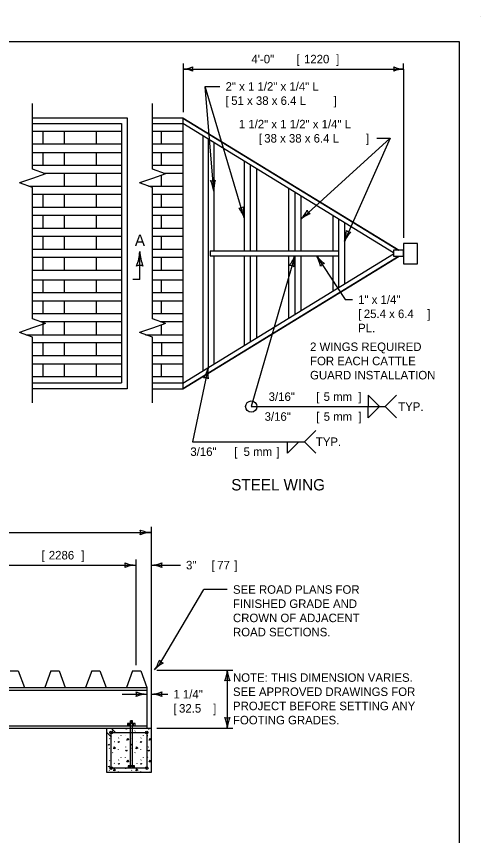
# Model space of a CAD drawing. Extents: x 49991.4 to 50021, y 49987.6 to 50011.4.
# Drawn here: x 50013.63 to 50016.9, y 49993.4 to 49999.18 of the extents above; entities that cross this region are included whole.
import ezdxf

# ---------------------------------------------------------------- set-up
doc = ezdxf.new("R2010")
doc.units = 0
for name, color, linetype in [('Level 1', 7, 'Continuous'), ('Level 2', 7, 'Continuous'), ('Level 3', 7, 'Continuous'), ('Level 4', 7, 'Continuous'), ('Level 6', 7, 'Continuous')]:
    doc.layers.add(name, color=color, linetype=linetype)

msp = doc.modelspace()

# ---------------------------------------------------------------- linework, layer by layer
at = {"layer": 'Level 1'}
for p, q in [((50016.9001, 49999.1756), (50016.9001, 49999.1756)), ((50013.7456, 49998.4611), (50014.4107, 49998.4611)), ((50014.4107, 49998.4611), (50014.4107, 49996.5518)), ((50014.5891, 49998.4611), (50014.8029, 49998.4611)), ((50014.8029, 49998.4611), (50016.3256, 49997.5269)), ((50014.8029, 49998.4611), (50014.8029, 49996.5517)), ((50013.7456, 49998.4211), (50014.3707, 49998.4211)), ((50014.3707, 49998.4211), (50014.3707, 49996.5923)), ((50014.5891, 49998.4211), (50014.8029, 49998.4211)), ((50014.8029, 49998.4223), (50016.2874, 49997.5115)), ((50014.3707, 49998.3652), (50013.7456, 49998.3652)), ((50013.8192, 49998.2744), (50013.8192, 49998.3652)), ((50013.9701, 49998.2744), (50013.9701, 49998.3652)), ((50014.1943, 49998.2744), (50014.1943, 49998.3652)), ((50014.8029, 49998.3652), (50014.5891, 49998.3652)), ((50014.6527, 49998.2744), (50014.6527, 49998.3652)), ((50014.9451, 49998.3351), (50014.9451, 49996.6777)), ((50014.3707, 49998.2744), (50013.7456, 49998.2744)), ((50014.8029, 49998.2744), (50014.5891, 49998.2744)), ((50014.9816, 49998.3127), (50014.9816, 49996.7001)), ((50015.0211, 49998.2884), (50015.0211, 49997.5238)), ((50013.7456, 49998.2165), (50014.3707, 49998.2165)), ((50013.8192, 49998.1264), (50013.8192, 49998.2165)), ((50013.9701, 49998.1264), (50013.9701, 49998.2165)), ((50014.1943, 49998.1264), (50014.1943, 49998.2165)), ((50014.5891, 49998.2165), (50014.8029, 49998.2165)), ((50014.6527, 49998.1264), (50014.6527, 49998.2165)), ((50015.2358, 49998.1567), (50015.2358, 49997.5238)), ((50013.7456, 49998.1264), (50014.3707, 49998.1264)), ((50014.5891, 49998.1264), (50014.8029, 49998.1264)), ((50015.2784, 49998.1306), (50015.2784, 49997.5238)), ((50015.321, 49998.1044), (50015.321, 49997.5238)), ((50013.8277, 49998.0696), (50014.3707, 49998.0696)), ((50013.9701, 49997.9788), (50013.9701, 49998.0696)), ((50014.1943, 49997.9788), (50014.1943, 49998.0696)), ((50014.6527, 49997.9788), (50014.6527, 49998.0563)), ((50014.6709, 49998.0696), (50014.8029, 49998.0696)), ((50013.7182, 49997.9788), (50014.3707, 49997.9788)), ((50014.5615, 49997.9788), (50014.8029, 49997.9788)), ((50013.7456, 49997.9219), (50014.3707, 49997.9219)), ((50013.8192, 49997.831), (50013.8192, 49997.9219)), ((50013.9701, 49997.831), (50013.9701, 49997.9219)), ((50014.1943, 49997.831), (50014.1943, 49997.9219)), ((50014.5891, 49997.9219), (50014.8029, 49997.9219)), ((50014.6527, 49997.831), (50014.6527, 49997.9219)), ((50015.5482, 49997.965), (50015.5482, 49997.5238)), ((50015.5908, 49997.9389), (50015.5908, 49997.5238)), ((50015.6336, 49997.9127), (50015.6336, 49997.5238)), ((50013.7456, 49997.831), (50014.3707, 49997.831)), ((50014.5891, 49997.831), (50014.8029, 49997.831)), ((50013.7456, 49997.7742), (50014.3707, 49997.7742)), ((50013.8192, 49997.6832), (50013.8192, 49997.7742)), ((50013.9701, 49997.6832), (50013.9701, 49997.7742)), ((50014.1943, 49997.6832), (50014.1943, 49997.7742)), ((50014.5891, 49997.7742), (50014.8029, 49997.7742)), ((50014.6527, 49997.6832), (50014.6527, 49997.7742)), ((50015.8607, 49997.7733), (50015.8607, 49997.5238)), ((50015.9006, 49997.7488), (50015.9006, 49997.2639)), ((50013.7456, 49997.6832), (50014.3707, 49997.6832)), ((50014.5891, 49997.6832), (50014.8029, 49997.6832)), ((50015.9409, 49997.7241), (50015.9409, 49997.2886)), ((50013.7456, 49997.6265), (50014.3707, 49997.6265)), ((50013.8192, 49997.5355), (50013.8192, 49997.6265)), ((50013.9701, 49997.5355), (50013.9701, 49997.6265)), ((50014.1943, 49997.5355), (50014.1943, 49997.6265)), ((50014.5891, 49997.6265), (50014.8029, 49997.6265)), ((50014.6527, 49997.5355), (50014.6527, 49997.6265)), ((50013.7456, 49997.5355), (50014.3707, 49997.5355)), ((50014.5891, 49997.5355), (50014.8029, 49997.5355)), ((50014.9948, 49997.5238), (50015.9006, 49997.5238)), ((50014.9948, 49997.5238), (50014.9948, 49997.489)), ((50013.7456, 49997.4788), (50014.3707, 49997.4788)), ((50013.8192, 49997.3862), (50013.8192, 49997.4788)), ((50013.9701, 49997.3862), (50013.9701, 49997.4788)), ((50014.1943, 49997.3862), (50014.1943, 49997.4788)), ((50014.5891, 49997.4788), (50014.8029, 49997.4788)), ((50014.6527, 49997.3862), (50014.6527, 49997.4788)), ((50014.8029, 49996.5904), (50016.2874, 49997.5012)), ((50014.8029, 49996.5517), (50016.3256, 49997.486)), ((50014.9948, 49997.489), (50015.9006, 49997.489)), ((50015.0211, 49997.489), (50015.0211, 49996.7243)), ((50015.2358, 49997.489), (50015.2358, 49996.856)), ((50015.2784, 49997.489), (50015.2784, 49996.8822)), ((50015.321, 49997.489), (50015.321, 49996.9083)), ((50015.5482, 49997.489), (50015.5482, 49997.0477)), ((50015.5908, 49997.489), (50015.5908, 49997.0738)), ((50015.6336, 49997.489), (50015.6336, 49997.1001)), ((50015.8607, 49997.489), (50015.8607, 49997.2394)), ((50013.7456, 49997.3862), (50014.3707, 49997.3862)), ((50014.5891, 49997.3862), (50014.8029, 49997.3862)), ((50013.7456, 49997.3196), (50014.3707, 49997.3196)), ((50013.8192, 49997.2287), (50013.8192, 49997.3196)), ((50013.9701, 49997.2287), (50013.9701, 49997.3196)), ((50014.1943, 49997.2287), (50014.1943, 49997.3196)), ((50014.5891, 49997.3196), (50014.8029, 49997.3196)), ((50014.6527, 49997.2287), (50014.6527, 49997.3196)), ((50013.7456, 49997.2287), (50014.3707, 49997.2287)), ((50014.5891, 49997.2287), (50014.8029, 49997.2287)), ((50013.7456, 49997.1719), (50014.3707, 49997.1719)), ((50013.8192, 49997.081), (50013.8192, 49997.1719)), ((50013.9701, 49997.081), (50013.9701, 49997.1719)), ((50014.1943, 49997.081), (50014.1943, 49997.1719)), ((50014.5891, 49997.1719), (50014.8029, 49997.1719)), ((50014.6527, 49997.081), (50014.6527, 49997.1719)), ((50013.7456, 49997.081), (50014.3707, 49997.081)), ((50014.5891, 49997.081), (50014.8029, 49997.081)), ((50013.8023, 49997.0242), (50014.3707, 49997.0242)), ((50013.8192, 49996.9316), (50013.8192, 49997.0242)), ((50013.9701, 49996.9316), (50013.9701, 49997.0242)), ((50014.1943, 49996.9316), (50014.1943, 49997.0242)), ((50014.6447, 49997.0242), (50014.8029, 49997.0242)), ((50014.6527, 49996.9316), (50014.6527, 49997.0016)), ((50013.6979, 49996.9316), (50014.3707, 49996.9316)), ((50013.7456, 49996.8766), (50014.3707, 49996.8766)), ((50013.8192, 49996.7855), (50013.8192, 49996.8766)), ((50013.9701, 49996.7855), (50013.9701, 49996.8766)), ((50014.1943, 49996.7855), (50014.1943, 49996.8766)), ((50014.5403, 49996.9316), (50014.8029, 49996.9316)), ((50014.5891, 49996.8766), (50014.8029, 49996.8766)), ((50014.6527, 49996.8766), (50014.6527, 49996.7855)), ((50013.7456, 49996.7855), (50014.3707, 49996.7855)), ((50014.5891, 49996.7855), (50014.8029, 49996.7855)), ((50013.7456, 49996.7279), (50014.3707, 49996.7279)), ((50013.8192, 49996.6378), (50013.8192, 49996.7279)), ((50013.9701, 49996.6378), (50013.9701, 49996.7279)), ((50014.1943, 49996.6378), (50014.1943, 49996.7279)), ((50014.5891, 49996.7279), (50014.8029, 49996.7279)), ((50014.6527, 49996.6378), (50014.6527, 49996.7279)), ((50013.7456, 49996.6378), (50014.3707, 49996.6378)), ((50013.7456, 49996.5923), (50014.3707, 49996.5923)), ((50014.5891, 49996.6378), (50014.8029, 49996.6378)), ((50014.5891, 49996.5923), (50014.8029, 49996.5923)), ((50013.7456, 49996.5523), (50014.4107, 49996.5523)), ((50014.5891, 49996.5517), (50014.8019, 49996.5517)), ((50014.8019, 49996.5517), (50014.8029, 49996.5517)), ((50013.5871, 49994.5622), (50013.6444, 49994.5622)), ((50013.6444, 49994.5622), (50013.6877, 49994.4468)), ((50013.8746, 49994.5622), (50013.8312, 49994.4468)), ((50013.8746, 49994.5622), (50013.9319, 49994.5622)), ((50013.9319, 49994.5622), (50013.9752, 49994.4468)), ((50014.162, 49994.5622), (50014.1186, 49994.4468)), ((50014.162, 49994.5622), (50014.2194, 49994.5622)), ((50014.2194, 49994.5622), (50014.2628, 49994.4468)), ((50014.4495, 49994.5635), (50014.4056, 49994.4468)), ((50014.4495, 49994.5635), (50014.507, 49994.5635)), ((50014.507, 49994.5635), (50014.5501, 49994.4468)), ((50010.9693, 49994.4468), (50014.5501, 49994.4468)), ((50010.9693, 49994.4271), (50014.5501, 49994.4271)), ((50014.5501, 49994.4468), (50014.5501, 49994.1596)), ((50010.9693, 49994.1748), (50014.5501, 49994.1748)), ((50014.4097, 49994.1756), (50014.4722, 49994.1756)), ((50014.4097, 49994.1748), (50014.4097, 49994.1756)), ((50014.4498, 49994.1926), (50014.414, 49994.1926)), ((50014.414, 49994.1926), (50014.414, 49994.1756)), ((50014.4247, 49994.1756), (50014.4247, 49994.1926)), ((50014.4341, 49993.8798), (50014.4341, 49994.2114)), ((50014.4498, 49994.2103), (50014.4341, 49994.2114)), ((50014.4498, 49994.2073), (50014.4341, 49994.2084)), ((50014.4498, 49994.2044), (50014.4341, 49994.2055)), ((50014.4498, 49994.2014), (50014.4341, 49994.2025)), ((50014.4498, 49994.1984), (50014.4341, 49994.1995)), ((50014.4498, 49994.1955), (50014.4341, 49994.1966)), ((50014.4498, 49993.8801), (50014.4498, 49994.2103)), ((50014.4678, 49994.1926), (50014.4498, 49994.1926)), ((50014.4566, 49994.1756), (50014.4566, 49994.1926)), ((50014.4678, 49994.1756), (50014.4678, 49994.1926)), ((50014.4722, 49994.1748), (50014.4722, 49994.1756)), ((50010.9398, 49994.1596), (50014.5796, 49994.1596)), ((50014.2673, 49994.1284), (50014.3005, 49994.0951)), ((50014.2986, 49994.1596), (50014.3317, 49994.1264)), ((50014.448, 49993.8944), (50014.4192, 49993.894)), ((50014.4192, 49993.894), (50014.4194, 49993.8795)), ((50014.4194, 49993.8795), (50014.4482, 49993.8801)), ((50014.4283, 49993.8796), (50014.428, 49993.8942)), ((50014.4624, 49993.8947), (50014.448, 49993.8944)), ((50014.4482, 49993.8801), (50014.4626, 49993.8803)), ((50014.4536, 49993.8803), (50014.4534, 49993.8946)), ((50014.4626, 49993.8803), (50014.4624, 49993.8947))]:
    msp.add_line(p, q, dxfattribs=at)
for points in [[(49999.3835, 49998.9992), (50016.7501, 49998.9992), (50016.7501, 49987.7988), (49999.3835, 49987.7988)], [(50016.3578, 49997.5749), (50016.3578, 49997.4326), (50016.4569, 49997.4326), (50016.4569, 49997.5749)], [(50016.2874, 49997.5269), (50016.2874, 49997.486), (50016.3578, 49997.486), (50016.3578, 49997.5269)], [(50014.2673, 49994.1596), (50014.5798, 49994.1596), (50014.5798, 49993.8471), (50014.2673, 49993.8471)], [(50014.2986, 49994.1284), (50014.5486, 49994.1284), (50014.5486, 49993.8784), (50014.2986, 49993.8784)]]:
    msp.add_lwpolyline(points, close=True, dxfattribs=at)
for centre in [(50014.2986, 49994.1283), (50014.5486, 49994.1283), (50014.2986, 49993.8783), (50014.5486, 49993.8783)]:
    msp.add_circle(centre, 0.00937, dxfattribs=at)
at = {"layer": 'Level 3'}
for p, q in [((50014.8046, 49998.8446), (50014.8046, 49998.5011)), ((50016.3573, 49998.8046), (50016.3573, 49998.8446)), ((50016.3573, 49998.8046), (50016.3573, 49998.4863)), ((50016.3573, 49998.4863), (50016.3573, 49997.6149)), ((50016.2623, 49998.3163), (50015.6336, 49997.7451)), ((50016.2623, 49998.3163), (50015.9409, 49997.5909)), ((50016.1701, 49998.3163), (50016.2623, 49998.3163)), ((50015.5908, 49997.489), (50015.2854, 49996.4255)), ((50015.7449, 49997.489), (50015.9457, 49997.1793)), ((50015.9457, 49997.1793), (50015.9977, 49997.1793)), ((50014.9816, 49996.7001), (50014.8702, 49996.1778)), ((50016.1082, 49996.5055), (50016.1082, 49996.4255)), ((50016.1082, 49996.5055), (50016.1882, 49996.4255)), ((50016.2282, 49996.4255), (50016.3082, 49996.5055)), ((50015.2854, 49996.4255), (50016.2282, 49996.4255)), ((50016.1082, 49996.3455), (50016.1082, 49996.4255)), ((50016.1082, 49996.3455), (50016.1882, 49996.4255)), ((50016.2282, 49996.4255), (50016.3082, 49996.3455)), ((50015.6598, 49996.1778), (50015.7398, 49996.2578)), ((50014.8702, 49996.1778), (50015.6598, 49996.1778)), ((50015.5398, 49996.0978), (50015.5398, 49996.1778)), ((50015.5398, 49996.0978), (50015.6198, 49996.1778)), ((50015.6598, 49996.1778), (50015.7398, 49996.0978)), ((50014.5798, 49995.579), (50014.5798, 49994.1996)), ((50010.938, 49995.539), (50014.5798, 49995.539)), ((50014.4721, 49995.3483), (50014.4721, 49994.6035)), ((50011.04, 49995.3083), (50014.4721, 49995.3083)), ((50014.5798, 49995.3083), (50014.7857, 49995.3083)), ((50014.6316, 49994.5968), (50014.9515, 49995.1364)), ((50015.1164, 49995.1364), (50014.9515, 49995.1364)), ((50014.6198, 49994.5687), (50015.1564, 49994.5687)), ((50015.1164, 49994.5687), (50015.1164, 49994.1591)), ((50014.3767, 49994.399), (50014.5501, 49994.399)), ((50014.5798, 49994.3988), (50014.6969, 49994.3988)), ((50014.5798, 49994.1996), (50014.5798, 49994.1596)), ((50014.3088, 49994.1389), (50014.3099, 49994.1413)), ((50014.3661, 49994.1089), (50014.3672, 49994.1073)), ((50014.3972, 49994.1083), (50014.3982, 49994.1067)), ((50014.4664, 49994.1389), (50014.4675, 49994.1413)), ((50014.5237, 49994.1089), (50014.5248, 49994.1073)), ((50014.5548, 49994.1083), (50014.5559, 49994.1067)), ((50014.6196, 49994.1591), (50015.1564, 49994.1591)), ((50014.2873, 49994.083), (50014.2883, 49994.0854)), ((50014.3206, 49994.066), (50014.3216, 49994.0644)), ((50014.3485, 49994.0591), (50014.3517, 49994.0657)), ((50014.357, 49994.0617), (50014.3485, 49994.0591)), ((50014.3504, 49994.0892), (50014.3515, 49994.0916)), ((50014.3517, 49994.0657), (50014.357, 49994.0617)), ((50014.4449, 49994.083), (50014.4459, 49994.0854)), ((50014.4782, 49994.066), (50014.4792, 49994.0644)), ((50014.5061, 49994.0591), (50014.5093, 49994.0657)), ((50014.5147, 49994.0617), (50014.5061, 49994.0591)), ((50014.508, 49994.0892), (50014.5091, 49994.0916)), ((50014.5093, 49994.0657), (50014.5147, 49994.0617)), ((50014.2846, 49994.0154), (50014.2857, 49994.0178)), ((50014.3479, 49994.0087), (50014.3482, 49994.0063)), ((50014.4017, 49994.0263), (50014.4028, 49994.0287)), ((50014.4422, 49994.0154), (50014.4433, 49994.0178)), ((50014.5055, 49994.0087), (50014.5058, 49994.0063)), ((50014.5593, 49994.0263), (50014.5604, 49994.0287)), ((50014.2873, 49993.9286), (50014.2883, 49993.931)), ((50014.3088, 49993.9845), (50014.3099, 49993.9869)), ((50014.3504, 49993.9347), (50014.3515, 49993.9371)), ((50014.3661, 49993.9545), (50014.3672, 49993.9529)), ((50014.3972, 49993.9539), (50014.3982, 49993.9523)), ((50014.4449, 49993.9286), (50014.4459, 49993.931)), ((50014.4664, 49993.9845), (50014.4675, 49993.9869)), ((50014.508, 49993.9347), (50014.5091, 49993.9371)), ((50014.5237, 49993.9545), (50014.5248, 49993.9529)), ((50014.5548, 49993.9539), (50014.5559, 49993.9523)), ((50014.3206, 49993.9115), (50014.3216, 49993.9099)), ((50014.3485, 49993.9046), (50014.3517, 49993.9113)), ((50014.357, 49993.9073), (50014.3485, 49993.9046)), ((50014.3517, 49993.9113), (50014.357, 49993.9073)), ((50014.4017, 49993.8718), (50014.4028, 49993.8742)), ((50014.4782, 49993.9115), (50014.4792, 49993.9099)), ((50014.5061, 49993.9046), (50014.5093, 49993.9113)), ((50014.5147, 49993.9073), (50014.5061, 49993.9046)), ((50014.5093, 49993.9113), (50014.5147, 49993.9073)), ((50014.5593, 49993.8718), (50014.5604, 49993.8742)), ((50014.2846, 49993.8609), (50014.2857, 49993.8633)), ((50014.3479, 49993.8542), (50014.3482, 49993.8518)), ((50014.4422, 49993.8609), (50014.4433, 49993.8633)), ((50014.5055, 49993.8542), (50014.5058, 49993.8518))]:
    msp.add_line(p, q, dxfattribs=at)
for points in [[(50014.8046, 49998.8046), (50016.3573, 49998.8046)], [(50015.2358, 49997.7569), (50014.9617, 49998.6818)], [(50014.9617, 49998.6818), (50015.0642, 49998.6818)], [(50015.0211, 49997.9434), (50014.9617, 49998.6818)], [(50014.4022, 49994.1528), (50014.4054, 49994.1594), (50014.4108, 49994.1554), (50014.4022, 49994.1528)], [(50014.5599, 49994.1528), (50014.563, 49994.1594), (50014.5684, 49994.1554), (50014.5599, 49994.1528)], [(50014.2793, 49994.04), (50014.2825, 49994.0467), (50014.2878, 49994.0427), (50014.2793, 49994.04)], [(50014.4089, 49994.0758), (50014.4161, 49994.0894), (50014.4217, 49994.0769), (50014.4092, 49994.0758)], [(50014.4369, 49994.04), (50014.4401, 49994.0467), (50014.4454, 49994.0427), (50014.4369, 49994.04)], [(50014.5665, 49994.0758), (50014.5737, 49994.0894), (50014.5793, 49994.0769), (50014.5668, 49994.0758)], [(50014.317, 49994.0126), (50014.3191, 49994.0278), (50014.3286, 49994.018), (50014.3172, 49994.0127)], [(50014.4022, 49993.9983), (50014.4054, 49994.005), (50014.4108, 49994.001), (50014.4022, 49993.9983)], [(50014.4746, 49994.0126), (50014.4767, 49994.0278), (50014.4863, 49994.018), (50014.4749, 49994.0127)], [(50014.5599, 49993.9983), (50014.563, 49994.005), (50014.5684, 49994.001), (50014.5599, 49993.9983)], [(50014.4089, 49993.9214), (50014.4161, 49993.935), (50014.4217, 49993.9225), (50014.4092, 49993.9214)], [(50014.5665, 49993.9214), (50014.5737, 49993.935), (50014.5793, 49993.9225), (50014.5668, 49993.9214)], [(50014.2793, 49993.8856), (50014.2825, 49993.8922), (50014.2878, 49993.8882), (50014.2793, 49993.8856)], [(50014.317, 49993.8582), (50014.3191, 49993.8734), (50014.3286, 49993.8635), (50014.3172, 49993.8583)], [(50014.4369, 49993.8856), (50014.4401, 49993.8922), (50014.4454, 49993.8882), (50014.4369, 49993.8856)], [(50014.4746, 49993.8582), (50014.4767, 49993.8734), (50014.4863, 49993.8635), (50014.4749, 49993.8583)], [(50014.4038, 49993.8471), (50014.4054, 49993.8505), (50014.41, 49993.8471)], [(50014.5614, 49993.8471), (50014.563, 49993.8505), (50014.5676, 49993.8471)]]:
    msp.add_lwpolyline(points, dxfattribs=at)
msp.add_circle((50015.2854, 49996.4254), 0.04, dxfattribs=at)
for centre, radius, start, end in [((50014.794, 49999.0112), 0.2069, 272.92748, 292.17733), ((50014.7968, 49998.6074), 0.1974, 67.55618, 87.73969), ((50014.9184, 49998.8048), 0.0486, 162.23899, 197.96135), ((50016.3651, 49999.0018), 0.1974, 247.55618, 267.73969), ((50016.2435, 49998.8044), 0.0486, 342.23899, 17.96135), ((50016.3679, 49998.598), 0.2069, 92.92748, 112.17733), ((50015.0108, 49998.0712), 0.0548, 256.73487, 292.45723), ((50014.7901, 49997.9133), 0.233, 7.42336, 26.67321), ((50015.2433, 49997.9521), 0.2223, 162.05206, 182.23557), ((50015.1984, 49997.8795), 0.0548, 269.09819, 304.82055), ((50015.0166, 49997.678), 0.233, 19.78668, 39.03653), ((50015.451, 49997.8129), 0.2223, 174.41538, 194.59889), ((50015.467, 49997.908), 0.233, 315.63554, 334.88539), ((50015.7277, 49997.8322), 0.0548, 204.94705, 240.66941), ((50015.7778, 49997.5759), 0.2223, 110.26424, 130.44775), ((50015.7227, 49997.6726), 0.233, 339.46817, 358.71802), ((50016.1412, 49997.4944), 0.2223, 134.09687, 154.28038), ((50015.9917, 49997.7086), 0.0548, 228.77968, 264.50204), ((50015.3798, 49997.5591), 0.2223, 321.4338, 341.61731), ((50015.8177, 49997.4358), 0.233, 166.8051, 186.05495), ((50015.5535, 49997.3758), 0.2223, 10.41873, 30.60224), ((50015.9339, 49997.6253), 0.233, 215.79003, 235.03988), ((50015.5554, 49997.3658), 0.0548, 56.11661, 91.83897), ((50015.8146, 49997.3814), 0.0548, 105.10154, 140.8239), ((50014.7659, 49996.7539), 0.2223, 325.80668, 345.99019), ((50015.2118, 49996.6643), 0.233, 171.17798, 190.42783), ((50014.9557, 49996.5745), 0.0548, 60.48949, 96.21185), ((50014.589, 49995.7611), 0.2223, 247.45601, 267.63952), ((50014.4516, 49995.539), 0.0548, 342.13882, 17.86118), ((50014.5913, 49995.3063), 0.233, 92.82731, 112.07716), ((50014.4813, 49995.5304), 0.2223, 247.45601, 267.63952), ((50014.3439, 49995.3083), 0.0548, 342.13882, 17.86118), ((50014.5683, 49995.541), 0.233, 272.82731, 292.07716), ((50014.708, 49995.3083), 0.0548, 162.13882, 197.86118), ((50014.4836, 49995.0756), 0.233, 92.82731, 112.07716), ((50014.5706, 49995.0862), 0.2223, 67.45601, 87.63952), ((50014.4167, 49994.7103), 0.233, 323.05126, 342.30111), ((50014.6849, 49994.6688), 0.0548, 212.36277, 248.08513), ((50014.7678, 49994.4211), 0.2223, 117.67996, 137.86347), ((50014.8943, 49994.5779), 0.2223, 337.45601, 357.63952), ((50015.3491, 49994.5802), 0.233, 182.82731, 202.07716), ((50015.1164, 49994.4405), 0.0548, 72.13882, 107.86118), ((50014.5593, 49994.6211), 0.2223, 247.45601, 267.63952), ((50014.4219, 49994.399), 0.0548, 342.13882, 17.86118), ((50014.5616, 49994.1662), 0.233, 92.82731, 112.07716), ((50014.5683, 49994.6315), 0.233, 272.82731, 292.07716), ((50014.5706, 49994.1766), 0.2223, 67.45601, 87.63952), ((50014.708, 49994.3988), 0.0548, 162.13882, 197.86118), ((50015.1164, 49994.2873), 0.0548, 252.13882, 287.86118), ((50014.8837, 49994.1476), 0.233, 2.82731, 22.07716), ((50015.3385, 49994.1499), 0.2223, 157.45601, 177.63952)]:
    msp.add_arc(centre, radius, start, end, dxfattribs=at)
at = {"layer": 'Level 4'}
for p, q in [((50014.8029, 49998.4587), (50016.3217, 49997.5269)), ((50014.8029, 49996.554), (50016.322, 49997.486))]:
    msp.add_line(p, q, dxfattribs=at)
at = {"layer": 'Level 6'}
for p, q in [((50013.7456, 49998.0987), (50013.7456, 49998.5611)), ((50014.5891, 49998.0986), (50014.5891, 49998.5611)), ((50013.837, 49998.0663), (50013.7456, 49998.0987)), ((50014.6805, 49998.0662), (50014.5891, 49998.0986)), ((50013.7456, 49998.0339), (50013.6542, 49998.0015)), ((50013.837, 49998.0663), (50013.7456, 49998.0339)), ((50014.5891, 49998.0338), (50014.4977, 49998.0014)), ((50014.6805, 49998.0662), (50014.5891, 49998.0338)), ((50013.7456, 49997.9691), (50013.6542, 49998.0015)), ((50014.5891, 49997.969), (50014.4977, 49998.0014)), ((50013.7456, 49997.0443), (50013.7456, 49997.9691)), ((50014.5891, 49997.0439), (50014.5891, 49997.969)), ((50014.4998, 49997.3219), (50014.4998, 49997.5177)), ((50014.4998, 49997.3219), (50014.4507, 49997.3219)), ((50013.837, 49997.0119), (50013.7456, 49997.0443)), ((50013.837, 49997.0119), (50013.7456, 49996.9795)), ((50014.6805, 49997.0115), (50014.5891, 49997.0439)), ((50014.6805, 49997.0115), (50014.5891, 49996.9791)), ((50013.7456, 49996.9795), (50013.6542, 49996.9471)), ((50013.7456, 49996.9147), (50013.6542, 49996.9471)), ((50014.5891, 49996.9791), (50014.4977, 49996.9467)), ((50014.5891, 49996.9143), (50014.4977, 49996.9467)), ((50013.7456, 49996.4523), (50013.7456, 49996.9147)), ((50014.5891, 49996.4517), (50014.5891, 49996.9143))]:
    msp.add_line(p, q, dxfattribs=at)
for centre, radius, start, end in [((50014.2036, 49997.5299), 0.2964, 337.45601, 357.63952), ((50014.8101, 49997.533), 0.3107, 182.82731, 202.07716), ((50014.4998, 49997.3467), 0.073, 72.13882, 107.86118)]:
    msp.add_arc(centre, radius, start, end, dxfattribs=at)

# ---------------------------------------------------------------- texts
at = {"layer": 'Level 2'}
for s, height, p in [('4\'-0" ', 0.06, (50015.2863, 49998.8446)), ('[', 0.06, (50015.603, 49998.8446)), ('1220', 0.06, (50015.6563, 49998.8446)), (']', 0.06, (50015.8827, 49998.8446)), ('2" x 1 1/2" x 1/4" L', 0.06, (50015.1042, 49998.6518)), ('[', 0.06, (50015.1042, 49998.5518)), ('51 x 38 x 6.4 L', 0.06, (50015.1439, 49998.5518)), (']', 0.06, (50015.8652, 49998.5518)), ('1 1/2" x 1 1/2" x 1/4" L', 0.06, (50015.1974, 49998.3863)), ('[', 0.06, (50015.3392, 49998.2863)), ('38 x 38 x 6.4 L', 0.06, (50015.3766, 49998.2863)), (']', 0.06, (50016.0927, 49998.2863)), ('A', 0.08, (50014.4655, 49997.5577)), ('1" x 1/4"', 0.06, (50016.0377, 49997.1493)), ('[', 0.06, (50016.0377, 49997.0493)), ('25.4 x 6.4', 0.06, (50016.0774, 49997.0493)), (']', 0.06, (50016.5249, 49997.0493)), ('PL.', 0.06, (50016.0377, 49996.9493)), ('2 WINGS REQUIRED', 0.06, (50015.6992, 49996.8171)), ('FOR EACH CATTLE', 0.06, (50015.6992, 49996.7171)), ('GUARD INSTALLATION', 0.06, (50015.6992, 49996.6171)), ('3/16" ', 0.06, (50015.4075, 49996.4655)), ('[', 0.06, (50015.7418, 49996.4655)), (']', 0.06, (50016.0395, 49996.4655)), ('5 mm', 0.06, (50015.7948, 49996.4655)), ('TYP. ', 0.06, (50016.32, 49996.3955)), (' 3/16" ', 0.06, (50015.3568, 49996.3255)), ('[', 0.06, (50015.7421, 49996.3255)), ('5 mm', 0.06, (50015.7951, 49996.3255)), (']', 0.06, (50016.0397, 49996.3255)), ('TYP. ', 0.06, (50015.7398, 49996.1478)), ('3/16" ', 0.06, (50014.8562, 49996.0778)), ('[', 0.06, (50015.1648, 49996.0778)), ('5 mm', 0.06, (50015.2311, 49996.0778)), (']', 0.06, (50015.4624, 49996.0778)), ('STEEL WING', 0.08, (50015.1442, 49995.8347)), ('[', 0.06, (50013.8078, 49995.3483)), ('2286', 0.06, (50013.8595, 49995.3483)), (']', 0.06, (50014.0875, 49995.3483)), ('3" ', 0.06, (50014.8257, 49995.2783)), ('[', 0.06, (50015.0057, 49995.2783)), ('77', 0.06, (50015.0454, 49995.2783)), (']', 0.06, (50015.1654, 49995.2783)), ('SEE ROAD PLANS FOR', 0.06, (50015.1564, 49995.1064)), ('FINISHED GRADE AND', 0.06, (50015.1564, 49995.0064)), ('CROWN OF ADJACENT', 0.06, (50015.1564, 49994.9064)), ('ROAD SECTIONS.', 0.06, (50015.1564, 49994.8064)), ('NOTE: THIS DIMENSION VARIES.', 0.06, (50015.1564, 49994.486)), ('1 1/4"', 0.06, (50014.7369, 49994.3688)), ('SEE APPROVED DRAWINGS FOR', 0.06, (50015.1564, 49994.386)), ('PROJECT BEFORE SETTING ANY', 0.06, (50015.1564, 49994.286)), ('[', 0.06, (50014.7369, 49994.2688)), ('32.5', 0.06, (50014.7766, 49994.2688)), (']', 0.06, (50015.0166, 49994.2688)), ('FOOTING GRADES.', 0.06, (50015.1564, 49994.186))]:
    msp.add_text(s, height=height, dxfattribs=at).set_placement(p)

doc.saveas('drawing.dxf')
